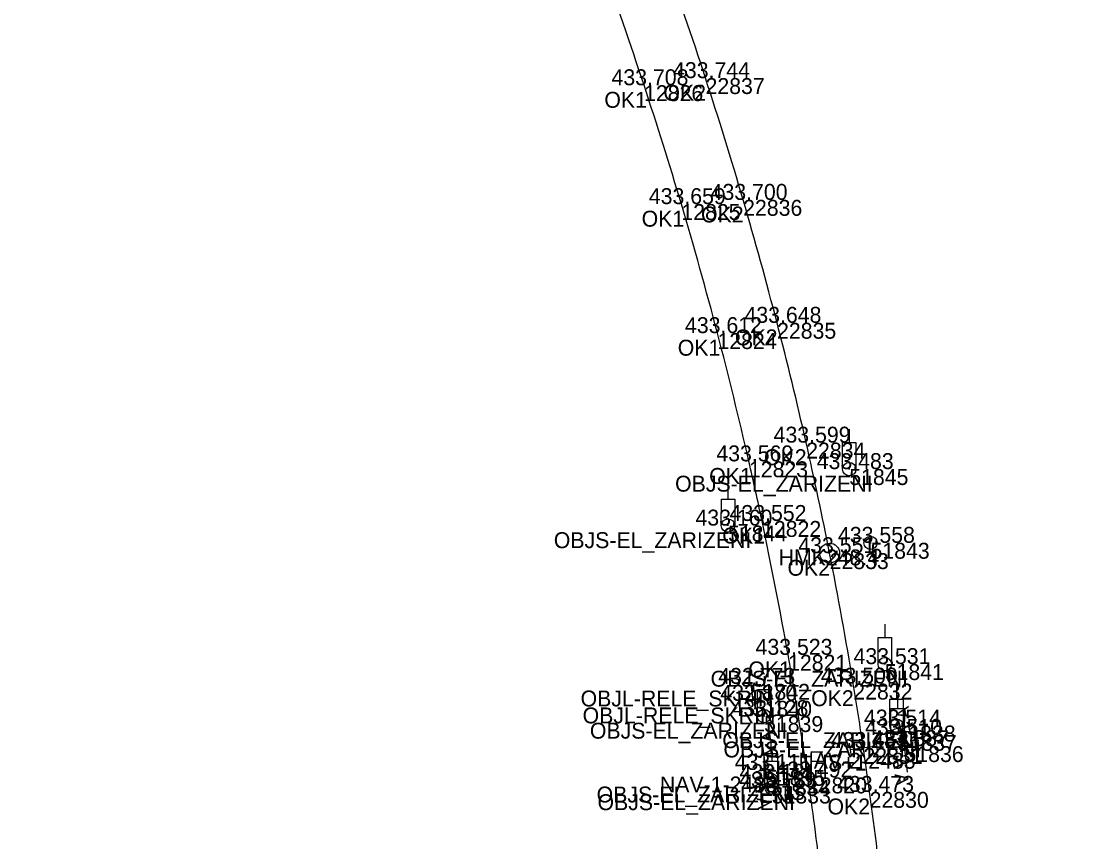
# Model space of a CAD drawing. Extents: x -678609 to -677678, y -1092434 to -1090394.
# Drawn here: x -678520.7 to -678440.7, y -1091094.7 to -1091032.8 of the extents above; entities that cross this region are included whole.
import ezdxf

# ---------------------------------------------------------------- set-up
doc = ezdxf.new("R2010")
doc.units = 0
for name, color, linetype in [('Vrstva 1', 7, 'Continuous'), ('Vrstva 12', 7, 'Continuous'), ('Vrstva 3', 7, 'Continuous'), ('Vrstva 50', 7, 'Continuous'), ('Vrstva 6', 7, 'Continuous'), ('Vrstva 60', 7, 'Continuous'), ('Vrstva 61', 7, 'Continuous'), ('Vrstva 62', 7, 'Continuous'), ('Vrstva 7', 7, 'Continuous')]:
    doc.layers.add(name, color=color, linetype=linetype)

msp = doc.modelspace()

# ---------------------------------------------------------------- linework, layer by layer
at = {"layer": 'Vrstva 1'}
for points in [[(-677965.496, -1092428.879), (-677967.797, -1092425.536), (-677972.061, -1092419.072), (-677977.322, -1092410.569), (-677981.838, -1092402.751), (-677986.704, -1092393.703), (-677991.483, -1092384.155), (-677995.988, -1092374.552), (-678000.171, -1092365.13), (-678004.016, -1092356.104), (-678007.818, -1092346.899), (-678011.742, -1092337.164), (-678015.49, -1092327.76), (-678018.88, -1092319.207), (-678022.344, -1092310.492), (-678025.402, -1092302.779), (-678026.464, -1092300.1), (-678028.077, -1092296.038), (-678031.512, -1092287.371), (-678035.084, -1092278.363), (-678038.67, -1092269.327), (-678042.194, -1092260.435), (-678045.92, -1092251.039), (-678049.17, -1092242.842), (-678052.721, -1092233.881), (-678056.517, -1092224.294), (-678060.132, -1092215.173), (-678063.853, -1092205.781), (-678067.583, -1092196.378), (-678071.228, -1092187.171), (-678074.63, -1092178.592), (-678078.072, -1092169.898), (-678081.186, -1092162.049), (-678084.714, -1092153.156), (-678085.214, -1092151.896), (-678088.664, -1092143.204), (-678090.488, -1092138.617), (-678093.752, -1092130.393), (-678097.354, -1092121.325), (-678101.031, -1092112.069), (-678104.652, -1092102.944), (-678108.085, -1092094.296), (-678111.85, -1092084.82), (-678115.34, -1092076.032), (-678118.88, -1092067.129), (-678122.701, -1092057.52), (-678126.454, -1092048.085), (-678130.123, -1092038.85), (-678134.041, -1092029.001), (-678137.702, -1092019.781), (-678141.32, -1092010.678), (-678144.944, -1092001.548), (-678148.535, -1091992.508), (-678152.219, -1091983.224), (-678155.782, -1091974.263), (-678159.368, -1091965.227), (-678163.152, -1091955.673), (-678166.795, -1091946.486), (-678170.636, -1091936.838), (-678174.45, -1091927.386), (-678178.214, -1091918.225), (-678182.025, -1091909.193), (-678185.864, -1091900.356), (-678190.297, -1091890.412), (-678194.61, -1091881.04), (-678198.42, -1091872.99), (-678201.545, -1091866.518), (-678205.759, -1091857.978), (-678210.041, -1091849.52), (-678214.137, -1091841.598), (-678218.678, -1091833.02), (-678223.386, -1091824.302), (-678228.113, -1091815.74), (-678232.892, -1091807.239), (-678237.677, -1091798.823), (-678242.572, -1091790.273), (-678247.479, -1091781.701), (-678252.5, -1091772.959), (-678257.408, -1091764.412), (-678262.301, -1091755.911), (-678267.382, -1091747.085), (-678272.061, -1091738.952), (-678276.673, -1091730.928), (-678281.004, -1091723.399), (-678285.636, -1091715.332), (-678290.569, -1091706.745), (-678295.171, -1091698.739), (-678299.178, -1091691.754), (-678304.61, -1091682.284), (-678309.177, -1091674.334), (-678309.937, -1091673.007), (-678310.561, -1091671.924), (-678316.583, -1091661.442), (-678321.552, -1091652.79), (-678326.066, -1091644.94), (-678331.096, -1091636.186), (-678336.134, -1091627.422), (-678341.161, -1091618.67), (-678346.238, -1091609.832), (-678351.199, -1091601.194), (-678356.259, -1091592.391), (-678361.268, -1091583.677), (-678366.286, -1091574.952), (-678371.377, -1091566.094), (-678376.478, -1091557.232), (-678380.944, -1091549.468), (-678384.949, -1091542.499), (-678389.877, -1091533.92), (-678391.414, -1091531.244), (-678395.308, -1091524.457), (-678398.306, -1091519.22), (-678402.185, -1091512.455), (-678406.978, -1091504.088), (-678412.058, -1091495.21), (-678417.073, -1091486.437), (-678421.589, -1091478.468), (-678426.389, -1091469.856), (-678431.189, -1091461.006), (-678435.595, -1091452.603), (-678440.544, -1091442.694), (-678444.836, -1091433.526), (-678448.934, -1091424.074), (-678452.669, -1091414.653), (-678456.154, -1091404.933), (-678459.235, -1091395.351), (-678461.832, -1091386.289), (-678463.326, -1091380.527), (-678465.421, -1091371.56), (-678467.307, -1091362.18), (-678468.866, -1091352.972), (-678470.152, -1091343.72), (-678471.153, -1091334.55), (-678471.892, -1091325.25), (-678472.382, -1091315.137), (-678472.532, -1091305.806), (-678472.394, -1091295.81), (-678471.983, -1091285.839), (-678471.345, -1091275.897), (-678470.529, -1091266.066), (-678469.612, -1091256.67), (-678468.464, -1091246.137), (-678467.202, -1091235.364), (-678466.061, -1091225.732), (-678464.975, -1091216.575), (-678463.791, -1091206.632), (-678462.596, -1091196.455), (-678461.478, -1091186.508), (-678460.532, -1091177.255), (-678460.072, -1091172.274), (-678459.605, -1091166.755), (-678458.931, -1091157.151), (-678458.542, -1091149.434), (-678458.257, -1091139.806), (-678458.238, -1091130.034), (-678458.461, -1091121.757), (-678458.959, -1091112.719), (-678459.555, -1091105.418), (-678460.034, -1091100.698), (-678460.437, -1091097.178), (-678461.423, -1091089.829), (-678462.916, -1091080.587), (-678464.88, -1091070.499), (-678465.869, -1091066.005), (-678468.24, -1091056.341), (-678470.962, -1091046.618), (-678473.775, -1091037.659), (-678476.989, -1091028.332), (-678480.323, -1091019.348), (-678483.945, -1091010.169), (-678487.772, -1091000.928), (-678492.089, -1090990.942), (-678495.909, -1090982.328), (-678497.227, -1090979.387), (-678500.625, -1090971.852), (-678504.735, -1090962.753), (-678508.481, -1090954.444), (-678512.885, -1090944.72), (-678517.191, -1090935.167), (-678521.191, -1090926.123), (-678525.007, -1090917.233), (-678528.921, -1090907.747), (-678532.48, -1090898.639), (-678535.334, -1090890.884), (-678536.977, -1090886.192), (-678540.173, -1090876.473), (-678543.056, -1090866.931), (-678545.501, -1090858.149), (-678547.9, -1090848.749), (-678550.224, -1090838.911), (-678552.414, -1090829.041), (-678553.208, -1090825.321), (-678554.732, -1090818.036), (-678556.89, -1090807.476), (-678558.822, -1090797.837), (-678560.452, -1090789.69), (-678561.922, -1090782.296), (-678563.916, -1090772.259), (-678565.622, -1090763.662), (-678567.403, -1090754.779), (-678569.242, -1090745.595), (-678571.088, -1090736.368), (-678573.01, -1090726.791), (-678574.935, -1090717.236), (-678576.897, -1090707.496), (-678578.789, -1090698.063), (-678580.69, -1090688.612), (-678582.626, -1090678.996), (-678584.566, -1090669.317), (-678586.613, -1090659.119), (-678588.601, -1090649.175), (-678590.471, -1090639.75), (-678592.407, -1090629.677), (-678594.085, -1090620.479), (-678595.569, -1090611.728), (-678596.962, -1090602.703), (-678598.178, -1090593.612), (-678598.923, -1090587.153), (-678599.862, -1090577.037), (-678600.45, -1090567.621), (-678600.742, -1090558.341), (-678600.747, -1090549.352), (-678600.47, -1090539.842), (-678599.882, -1090530.148), (-678599.147, -1090521.992), (-678598.154, -1090513.609), (-678597.583, -1090509.498), (-678596.284, -1090501.335), (-678594.495, -1090491.957), (-678592.377, -1090482.44), (-678589.799, -1090472.448), (-678586.94, -1090462.719), (-678583.675, -1090452.871), (-678579.952, -1090442.85), (-678576.03, -1090433.293), (-678571.81, -1090423.923), (-678567.428, -1090414.999), (-678562.935, -1090406.546), (-678558.467, -1090398.731), (-678556.056, -1090394.717)], [(-677960.407, -1092428.879), (-677963.182, -1092424.891), (-677968.577, -1092416.709), (-677973.83, -1092408.159), (-677978.652, -1092399.728), (-677983.174, -1092391.19), (-677987.576, -1092382.295), (-677991.662, -1092373.509), (-677995.54, -1092364.725), (-677999.476, -1092355.449), (-678003.003, -1092346.858), (-678006.395, -1092338.411), (-678008.067, -1092334.219), (-678011.064, -1092326.671), (-678014.792, -1092317.283), (-678018.171, -1092308.769), (-678021.37, -1092300.714), (-678022.15, -1092298.749), (-678025.47, -1092290.39), (-678029.004, -1092281.481), (-678032.788, -1092271.947), (-678036.424, -1092262.783), (-678040.085, -1092253.546), (-678043.642, -1092244.584), (-678046.801, -1092236.627), (-678050.195, -1092228.093), (-678054.046, -1092218.397), (-678057.867, -1092208.773), (-678061.639, -1092199.279), (-678064.93, -1092190.991), (-678068.514, -1092181.957), (-678072.169, -1092172.754), (-678075.998, -1092163.118), (-678079.446, -1092154.421), (-678082.715, -1092146.183), (-678084.415, -1092141.903), (-678086.215, -1092137.369), (-678089.716, -1092128.543), (-678093.324, -1092119.457), (-678097.157, -1092109.799), (-678100.719, -1092100.819), (-678103.851, -1092092.929), (-678107.353, -1092084.1), (-678110.917, -1092075.117), (-678114.445, -1092066.224), (-678118.414, -1092056.228), (-678122.02, -1092047.13), (-678125.636, -1092038.012), (-678129.256, -1092028.906), (-678132.87, -1092019.794), (-678136.678, -1092010.205), (-678140.28, -1092001.129), (-678143.886, -1091992.04), (-678147.539, -1091982.827), (-678151.475, -1091972.91), (-678155.192, -1091963.551), (-678158.501, -1091955.225), (-678162.135, -1091946.097), (-678165.937, -1091936.548), (-678169.613, -1091927.415), (-678172.984, -1091919.178), (-678176.44, -1091910.893), (-678180.321, -1091901.842), (-678184.486, -1091892.387), (-678188.925, -1091882.589), (-678193.211, -1091873.408), (-678197.777, -1091863.91), (-678202.145, -1091855.032), (-678206.559, -1091846.298), (-678211.053, -1091837.64), (-678215.664, -1091828.961), (-678220.332, -1091820.377), (-678225.039, -1091811.906), (-678229.832, -1091803.423), (-678234.981, -1091794.423), (-678239.053, -1091787.335), (-678241.838, -1091782.498), (-678246.331, -1091774.684), (-678251.234, -1091766.158), (-678256.347, -1091757.266), (-678261.447, -1091748.4), (-678266.632, -1091739.383), (-678271.025, -1091731.747), (-678275.991, -1091723.113), (-678281.085, -1091714.252), (-678285.98, -1091705.748), (-678290.883, -1091697.222), (-678295.451, -1091689.276), (-678300.007, -1091681.349), (-678300.914, -1091679.771), (-678305.04, -1091672.593), (-678308.7, -1091666.231), (-678313.556, -1091657.789), (-678316.068, -1091653.42), (-678316.993, -1091651.81), (-678322.044, -1091643.03), (-678327.115, -1091634.211), (-678332.268, -1091625.24), (-678337.319, -1091616.465), (-678342.335, -1091607.742), (-678347.325, -1091599.066), (-678352.433, -1091590.186), (-678357.506, -1091581.368), (-678362.522, -1091572.642), (-678367.557, -1091563.887), (-678372.598, -1091555.124), (-678377.69, -1091546.259), (-678382.672, -1091537.584), (-678387.77, -1091528.702), (-678389.169, -1091526.266), (-678390.169, -1091524.533), (-678393.179, -1091519.286), (-678397.885, -1091511.082), (-678402.799, -1091502.52), (-678408.007, -1091493.435), (-678412.937, -1091484.804), (-678417.667, -1091476.442), (-678422.716, -1091467.343), (-678425.167, -1091462.838), (-678430.24, -1091453.266), (-678432.126, -1091449.604), (-678436.36, -1091441.063), (-678440.361, -1091432.522), (-678444.297, -1091423.501), (-678448.136, -1091413.915), (-678451.669, -1091404.197), (-678454.524, -1091395.483), (-678456.78, -1091387.885), (-678459.365, -1091378.14), (-678461.464, -1091369.043), (-678463.242, -1091360.109), (-678464.77, -1091350.941), (-678466.089, -1091341.11), (-678467.052, -1091331.452), (-678467.742, -1091321.16), (-678468.055, -1091312.463), (-678468.127, -1091302.67), (-678467.921, -1091292.889), (-678467.749, -1091288.497), (-678467.241, -1091279.363), (-678466.648, -1091271.3), (-678465.797, -1091261.652), (-678464.831, -1091252.207), (-678464.223, -1091246.729), (-678463.165, -1091237.539), (-678462.036, -1091228.078), (-678460.892, -1091218.468), (-678459.787, -1091209.087), (-678458.694, -1091199.716), (-678457.614, -1091190.225), (-678456.66, -1091181.26), (-678456.281, -1091177.451), (-678455.952, -1091173.929), (-678455.206, -1091164.815), (-678454.581, -1091155.395), (-678454.118, -1091145.394), (-678453.901, -1091135.421), (-678453.979, -1091125.409), (-678454.402, -1091115.146), (-678455.186, -1091104.663), (-678455.673, -1091099.787), (-678456.767, -1091090.917), (-678457.238, -1091087.607), (-678457.998, -1091082.757), (-678459.784, -1091072.925), (-678461.552, -1091064.594), (-678463.747, -1091055.564), (-678466.304, -1091046.299), (-678469.139, -1091037.122), (-678472.303, -1091027.841), (-678475.727, -1091018.554), (-678479.35, -1091009.336), (-678482.775, -1091001.047), (-678486.387, -1090992.592), (-678490.197, -1090983.902), (-678491.752, -1090980.387), (-678492.985, -1090977.636), (-678496.181, -1090970.513), (-678500.433, -1090961.057), (-678504.034, -1090953.049), (-678508.106, -1090943.948), (-678512.142, -1090934.905), (-678516.166, -1090925.761), (-678520.147, -1090916.481), (-678524.11, -1090906.914), (-678527.451, -1090898.464), (-678529.964, -1090891.819), (-678532.422, -1090885.008), (-678535.399, -1090876.247), (-678538.303, -1090867.004), (-678541.153, -1090857.052), (-678543.633, -1090847.529), (-678545.802, -1090838.498), (-678548.265, -1090827.419), (-678548.842, -1090824.711), (-678550.268, -1090817.885), (-678552.124, -1090808.753), (-678554.093, -1090798.898), (-678556.124, -1090788.739), (-678556.564, -1090786.517), (-678557.74, -1090780.648), (-678559.414, -1090772.283), (-678561.24, -1090763.159), (-678563.162, -1090753.567), (-678565.213, -1090743.335), (-678567.131, -1090733.767), (-678569.134, -1090723.689), (-678570.724, -1090715.75), (-678572.442, -1090707.114), (-678574.335, -1090697.585), (-678575.503, -1090691.727), (-678576.872, -1090684.868), (-678578.681, -1090675.803), (-678580.416, -1090667.12), (-678582.342, -1090657.491), (-678584.313, -1090647.614), (-678586.284, -1090637.643), (-678588.202, -1090627.595), (-678589.956, -1090617.885), (-678591.585, -1090608.059), (-678593.059, -1090598.011), (-678594.312, -1090587.859), (-678595.291, -1090577.742), (-678595.945, -1090567.923), (-678596.268, -1090558.339), (-678596.283, -1090548.904), (-678595.988, -1090539.158), (-678595.39, -1090529.677), (-678594.52, -1090520.328), (-678593.843, -1090514.636), (-678593.367, -1090511.093), (-678591.867, -1090501.555), (-678590.51, -1090494.261), (-678588.644, -1090485.543), (-678587.943, -1090482.564), (-678585.526, -1090473.202), (-678582.777, -1090463.817), (-678579.919, -1090455.122), (-678576.621, -1090446.032), (-678572.806, -1090436.54), (-678568.84, -1090427.539), (-678564.339, -1090418.187), (-678559.621, -1090409.18), (-678555.084, -1090401.154), (-678551.203, -1090394.717)]]:
    msp.add_spline(points, degree=3, dxfattribs=at)
at = {"layer": 'Vrstva 12'}
msp.add_line((-678465.726, -1091082.778), (-678465.574, -1091084.055), dxfattribs=at)
at = {"layer": 'Vrstva 3'}
for p, q in [((-678456.318, -1091086.971), (-678456.178, -1091087.961)), ((-678458.298, -1091087.253), (-678458.158, -1091088.243)), ((-678456.248, -1091087.466), (-678458.228, -1091087.748)), ((-678460.498, -1091089.2), (-678460.365, -1091090.192)), ((-678462.481, -1091089.466), (-678462.348, -1091090.458)), ((-678460.432, -1091089.696), (-678462.414, -1091089.962))]:
    msp.add_line(p, q, dxfattribs=at)
at = {"layer": 'Vrstva 50'}
for p, q in [((-678458.302, -1091063.589), (-678458.302, -1091064.589)), ((-678458.252, -1091066.589), (-678458.352, -1091066.589)), ((-678467.448, -1091067.846), (-678467.448, -1091068.846)), ((-678467.398, -1091070.846), (-678467.498, -1091070.846)), ((-678455.624, -1091078.287), (-678455.624, -1091079.287)), ((-678455.574, -1091081.287), (-678455.674, -1091081.287)), ((-678464.726, -1091082.205), (-678464.726, -1091083.205)), ((-678454.741, -1091082.918), (-678454.741, -1091083.918)), ((-678454.655, -1091083.621), (-678454.655, -1091084.621)), ((-678464.676, -1091085.205), (-678464.776, -1091085.205)), ((-678454.691, -1091085.918), (-678454.791, -1091085.918)), ((-678454.605, -1091086.621), (-678454.705, -1091086.621)), ((-678464.219, -1091087.016), (-678464.219, -1091088.016)), ((-678464.152, -1091087.594), (-678464.152, -1091088.594)), ((-678464.169, -1091090.016), (-678464.269, -1091090.016)), ((-678464.102, -1091090.594), (-678464.202, -1091090.594))]:
    msp.add_line(p, q, dxfattribs=at)
for points in [[(-678458.808, -1091066.589), (-678458.802, -1091064.589), (-678457.795, -1091064.59), (-678457.796, -1091066.589)], [(-678467.954, -1091070.846), (-678467.948, -1091068.846), (-678466.941, -1091068.847), (-678466.942, -1091070.846)], [(-678456.13, -1091081.287), (-678456.124, -1091079.287), (-678455.117, -1091079.288), (-678455.118, -1091081.287)], [(-678465.232, -1091085.205), (-678465.226, -1091083.205), (-678464.219, -1091083.206), (-678464.22, -1091085.205)], [(-678455.247, -1091085.918), (-678455.241, -1091083.918), (-678454.234, -1091083.919), (-678454.235, -1091085.918)], [(-678455.161, -1091086.621), (-678455.155, -1091084.621), (-678454.148, -1091084.622), (-678454.149, -1091086.621)], [(-678464.725, -1091090.016), (-678464.719, -1091088.016), (-678463.712, -1091088.017), (-678463.713, -1091090.016)], [(-678464.658, -1091090.594), (-678464.652, -1091088.594), (-678463.645, -1091088.595), (-678463.646, -1091090.594)]]:
    msp.add_lwpolyline(points, dxfattribs=at)
for centre in [(-678458.302, -1091066.589), (-678467.448, -1091070.846), (-678455.624, -1091081.287), (-678464.726, -1091085.205), (-678454.741, -1091085.918), (-678454.655, -1091086.621), (-678464.219, -1091090.016), (-678464.152, -1091090.594)]:
    msp.add_circle(centre, 0.506, dxfattribs=at)
at = {"layer": 'Vrstva 6'}
for p, q in [((-678454.595, -1091085.542), (-678454.137, -1091087.468)), ((-678464.863, -1091087.3), (-678464.583, -1091089.26)), ((-678453.641, -1091087.408), (-678454.633, -1091087.528)), ((-678454.623, -1091087.584), (-678453.651, -1091087.352)), ((-678453.899, -1091089.434), (-678454.137, -1091087.468)), ((-678464.087, -1091089.193), (-678465.079, -1091089.327)), ((-678465.078, -1091089.331), (-678464.088, -1091089.189)), ((-678464.32, -1091091.222), (-678464.583, -1091089.26))]:
    msp.add_line(p, q, dxfattribs=at)
at = {"layer": 'Vrstva 60'}
for p, q in [((-678469.139, -1091037.122), (-678469.139, -1091037.122)), ((-678473.775, -1091037.659), (-678473.775, -1091037.659)), ((-678470.962, -1091046.618), (-678470.962, -1091046.618)), ((-678466.304, -1091046.299), (-678466.304, -1091046.299)), ((-678463.747, -1091055.564), (-678463.747, -1091055.564)), ((-678468.24, -1091056.341), (-678468.24, -1091056.341)), ((-678461.552, -1091064.594), (-678461.552, -1091064.594)), ((-678465.869, -1091066.005), (-678465.869, -1091066.005)), ((-678458.302, -1091066.589), (-678458.302, -1091066.589)), ((-678467.448, -1091070.846), (-678467.448, -1091070.846)), ((-678464.88, -1091070.499), (-678464.88, -1091070.499)), ((-678456.699, -1091072.146), (-678456.699, -1091072.146)), ((-678459.784, -1091072.925), (-678459.784, -1091072.925)), ((-678462.916, -1091080.587), (-678462.916, -1091080.587)), ((-678455.624, -1091081.287), (-678455.624, -1091081.287)), ((-678465.726, -1091082.778), (-678465.726, -1091082.778)), ((-678457.998, -1091082.757), (-678457.998, -1091082.757)), ((-678465.574, -1091084.055), (-678465.574, -1091084.055)), ((-678464.726, -1091085.205), (-678464.726, -1091085.205)), ((-678454.741, -1091085.918), (-678454.741, -1091085.918)), ((-678454.655, -1091086.621), (-678454.655, -1091086.621)), ((-678457.238, -1091087.607), (-678457.238, -1091087.607)), ((-678454.137, -1091087.468), (-678454.137, -1091087.468)), ((-678464.583, -1091089.26), (-678464.583, -1091089.26)), ((-678464.219, -1091090.016), (-678464.219, -1091090.016)), ((-678461.423, -1091089.829), (-678461.423, -1091089.829)), ((-678464.152, -1091090.594), (-678464.152, -1091090.594)), ((-678456.767, -1091090.917), (-678456.767, -1091090.917))]:
    msp.add_line(p, q, dxfattribs=at)
at = {"layer": 'Vrstva 7'}
msp.add_line((-678456.749, -1091072.146), (-678456.649, -1091072.146), dxfattribs=at)
for centre, radius in [((-678456.699, -1091072.146), 0.5), ((-678459.784, -1091072.925), 0.75)]:
    msp.add_circle(centre, radius, dxfattribs=at)

# ---------------------------------------------------------------- texts
at = {"layer": 'Vrstva 6'}
for rotation, p in [(103.37818, (-678453.164, -1091087.237)), (98.13003, (-678463.593, -1091089.119)), (276.91156, (-678455.13, -1091087.588)), (277.64476, (-678465.574, -1091089.393))]:
    msp.add_text('  A A ', height=1, rotation=rotation, dxfattribs=at).set_placement(p)
at = {"layer": 'Vrstva 60'}
for s, p in [('22837', (-678469.139, -1091038.322)), ('12826', (-678473.775, -1091038.859)), ('12825', (-678470.962, -1091047.818)), ('22836', (-678466.304, -1091047.499)), ('22835', (-678463.747, -1091056.764)), ('12824', (-678468.24, -1091057.541)), ('22834', (-678461.552, -1091065.794)), ('12823', (-678465.869, -1091067.205)), ('51845', (-678458.302, -1091067.789)), ('51844', (-678467.448, -1091072.046)), ('12822', (-678464.88, -1091071.699)), ('51843', (-678456.699, -1091073.346)), ('22833', (-678459.784, -1091074.125)), ('12821', (-678462.916, -1091081.787)), ('51841', (-678455.624, -1091082.487)), ('51842', (-678465.726, -1091083.978)), ('22832', (-678457.998, -1091083.957)), ('51840', (-678465.574, -1091085.255)), ('51839', (-678464.726, -1091086.405)), ('51838', (-678454.741, -1091087.118)), ('51837', (-678454.655, -1091087.821)), ('22831', (-678457.238, -1091088.807)), ('51836', (-678454.137, -1091088.668)), ('51835', (-678464.583, -1091090.46)), ('51834', (-678464.219, -1091091.216)), ('12820', (-678461.423, -1091091.029)), ('51833', (-678464.152, -1091091.794)), ('22830', (-678456.767, -1091092.117))]:
    msp.add_text(s, height=1.2, dxfattribs=at).set_placement(p)
at = {"layer": 'Vrstva 61'}
for s, p in [('433.708', (-678476.229, -1091037.659)), ('433.744', (-678471.59, -1091037.122)), ('433.700', (-678468.755, -1091046.299)), ('433.659', (-678473.416, -1091046.618)), ('433.648', (-678466.201, -1091055.564)), ('433.612', (-678470.688, -1091056.341)), ('433.599', (-678464.006, -1091064.594)), ('433.569', (-678468.323, -1091066.005)), ('433.483', (-678460.754, -1091066.589)), ('433.552', (-678467.328, -1091070.499)), ('433.160', (-678469.899, -1091070.846)), ('433.558', (-678459.153, -1091072.146)), ('433.551', (-678462.141, -1091072.925)), ('433.523', (-678465.368, -1091080.587)), ('433.531', (-678457.981, -1091081.287)), ('432.773', (-678468.178, -1091082.778)), ('433.500', (-678460.449, -1091082.757)), ('432.870', (-678468.025, -1091084.055)), ('433.128', (-678467.18, -1091085.205)), ('433.514', (-678457.192, -1091085.918)), ('433.510', (-678457.106, -1091086.621)), ('433.487', (-678459.69, -1091087.607)), ('433.387', (-678456.589, -1091087.468)), ('433.111', (-678466.94, -1091089.26)), ('433.159', (-678466.606, -1091090.594)), ('433.181', (-678466.576, -1091090.016)), ('433.492', (-678463.871, -1091089.829)), ('433.473', (-678459.219, -1091090.917))]:
    msp.add_text(s, height=1.2, dxfattribs=at).set_placement(p)
at = {"layer": 'Vrstva 62'}
for s, p in [('OK1', (-678476.77, -1091039.359)), ('OK2', (-678472.316, -1091038.822)), ('OK2', (-678469.481, -1091047.999)), ('OK1', (-678473.957, -1091048.318)), ('OK2', (-678466.924, -1091057.264)), ('OK1', (-678471.235, -1091058.041)), ('OK2', (-678464.729, -1091066.294)), ('OK1', (-678468.864, -1091067.705)), ('OBJS-EL_ZARIZENI', (-678471.436, -1091068.289)), ('OBJS-EL_ZARIZENI', (-678480.582, -1091072.546)), ('OK1', (-678467.875, -1091072.199)), ('HMK248.4', (-678463.626, -1091073.846)), ('OK2', (-678462.961, -1091074.625)), ('OK1', (-678465.911, -1091082.287)), ('OBJS-EL_ZARIZENI', (-678468.758, -1091082.987)), ('OBJL-RELE_SKRIN', (-678478.561, -1091084.478)), ('OK2', (-678461.175, -1091084.457)), ('OBJL-RELE_SKRIN', (-678478.409, -1091085.755)), ('OBJS-EL_ZARIZENI', (-678477.86, -1091086.905)), ('OBJS-EL_ZARIZENI', (-678467.875, -1091087.618)), ('OBJS-EL_ZARIZENI', (-678467.789, -1091088.321)), ('NAV-2-2483', (-678462.134, -1091089.168)), ('IS+1', (-678460.35, -1091089.307)), ('NAV-1-2483', (-678472.58, -1091090.96)), ('OBJS-EL_ZARIZENI', (-678477.353, -1091091.716)), ('IS', (-678463.152, -1091091.529)), ('OBJS-EL_ZARIZENI', (-678477.286, -1091092.294)), ('OK2', (-678459.944, -1091092.617))]:
    msp.add_text(s, height=1.2, dxfattribs=at).set_placement(p)

doc.saveas('drawing.dxf')
